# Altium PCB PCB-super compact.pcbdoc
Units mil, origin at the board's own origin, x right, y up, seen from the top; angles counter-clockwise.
Board outline 792.4 x 401.6 mil, 2 copper layers (Top Layer, Bottom Layer), stack 62.2 mil thick; 12 components, 10 nets, 38 pads, 0 vias.
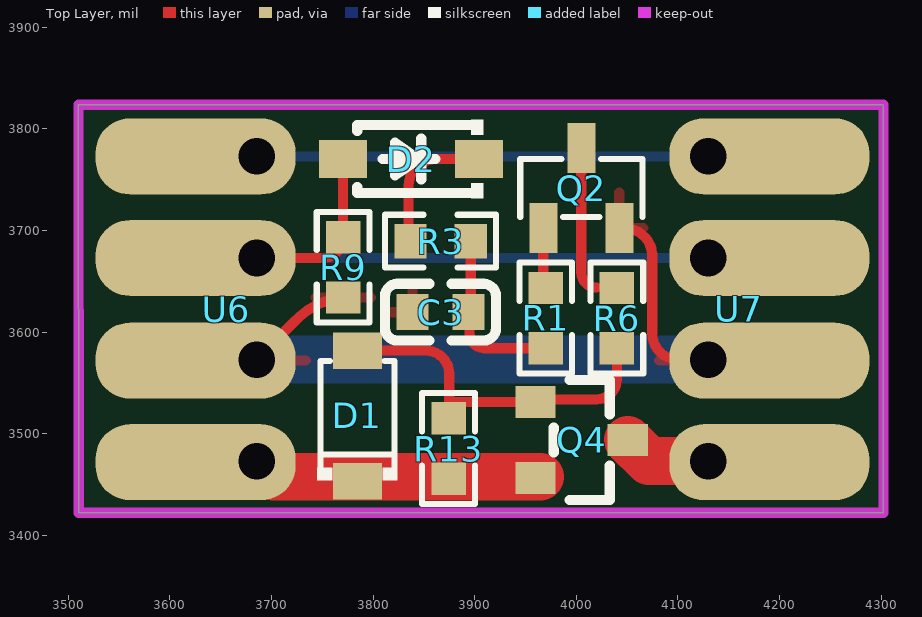
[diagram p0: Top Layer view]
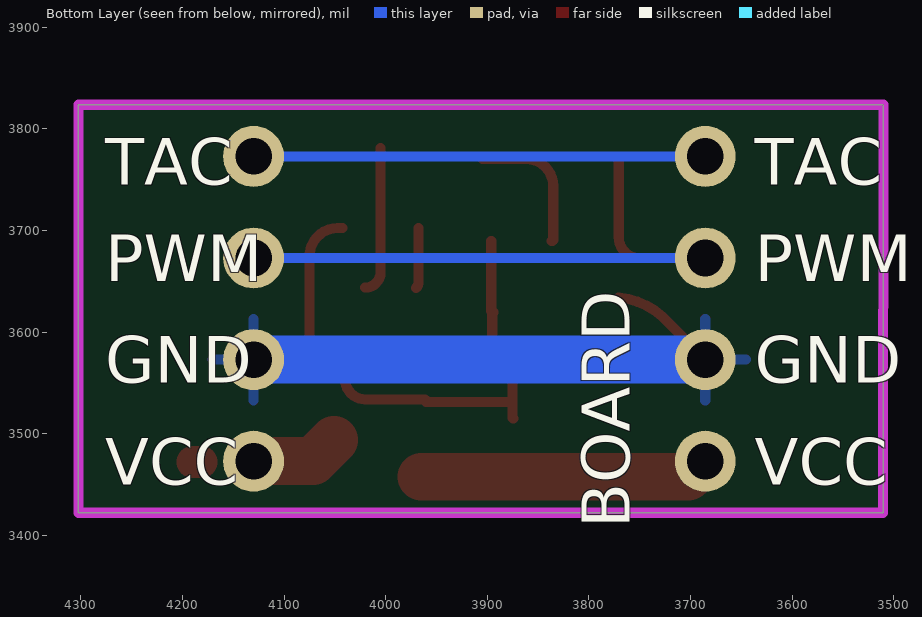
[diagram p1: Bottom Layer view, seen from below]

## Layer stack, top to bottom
Top Solder Mask Layer: solder mask 0.4, Dk 3.3
Top Layer: signal copper 1.4
Dielectric1: surface 59.4, FR4, Dk 4.5
Bottom Layer: signal copper 1.4
Bottom Solder Mask Layer: solder mask 0.4, Dk 3.3

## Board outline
3510,3823.8 4302.4,3823.8 4302.4,3422.2 3510.4,3422.2

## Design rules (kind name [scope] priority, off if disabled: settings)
BoardOutlineClearance copperThickness1oz [All] p0: genericclearance=10 ignorepadtopadclearanceinfootprint=FALSE except(0: Arc-SplitContinuation Track-SplitContinuation SMDPad-SplitContinuation THPad-SplitContinuation Via-SplitContinuation Fill-SplitContinuation Poly-SplitContinuation Region-SplitContinuation Text-SplitContinuation)
BoardOutlineClearance Plane_innerPlane [All] p0: genericclearance=10 ignorepadtopadclearanceinfootprint=FALSE except(0: Arc-SplitContinuation Track-SplitContinuation SMDPad-SplitContinuation THPad-SplitContinuation Via-SplitContinuation Fill-SplitContinuation Poly-SplitContinuation Region-SplitContinuation Text-SplitContinuation)
BoardOutlineClearance Copper_copperRegion [All] p0: genericclearance=10 ignorepadtopadclearanceinfootprint=FALSE except(0: Arc-SplitContinuation Track-SplitContinuation SMDPad-SplitContinuation THPad-SplitContinuation Via-SplitContinuation Fill-SplitContinuation Poly-SplitContinuation Region-SplitContinuation Text-SplitContinuation)
BoardOutlineClearance otherClearance [All] p0: genericclearance=10 ignorepadtopadclearanceinfootprint=FALSE except(0: Arc-SplitContinuation Track-SplitContinuation SMDPad-SplitContinuation THPad-SplitContinuation Via-SplitContinuation Fill-SplitContinuation Poly-SplitContinuation Region-SplitContinuation Text-SplitContinuation)
Clearance copperThickness1oz [All] p1: gap=7 ignorepadtopadclearanceinfootprint=FALSE
Clearance Plane_innerPlane [All] p1: gap=7 ignorepadtopadclearanceinfootprint=FALSE
Clearance Copper_copperRegion [All] p1: gap=7 ignorepadtopadclearanceinfootprint=FALSE
Clearance otherClearance [All] p1: gap=7 ignorepadtopadclearanceinfootprint=FALSE
DiffPairsRouting differentialPair [All] p1: maxuncoupledlength=10 minlimit=5.9843 maxlimit=Infinity mostfreqgap=5.9843 toplayer_minwidth=5 toplayer_prefwidth=10 toplayer_maxwidth=100 bottomlayer_minwidth=5 bottomlayer_prefwidth=10 bottomlayer_maxwidth=100
PasteMaskExpansion pasteMaskExpansion [All] p1: expansion=0
PlaneConnect innerPlane [All] p1: planeconnectstyle=Relief reliefexpansion=20 reliefentries=4 reliefconductorwidth=10 reliefairgap=10
PolygonConnect copperRegion [All] p1: connectstyle=Relief reliefentries=4 reliefconductorwidth=10 polygonreliefangle="90 Angle" airgapwidth=10
RoutingVias viaSize [All] p1: viastyle="Through Hole" holewidth=12.0078 minholewidth=11.811 maxholewidth=248.0314 width=12.0078 minwidth=11.811 maxwidth=248.0314
RoutingVias viaSize2oz [All] p1: viastyle="Through Hole" holewidth=23.622 minholewidth=19.685 maxholewidth=248.0314 width=23.622 minwidth=19.685 maxwidth=248.0314
RoutingVias "no vias" [All] p1: viastyle="Through Hole" holewidth=0.3938 minholewidth=0.3938 maxholewidth=0.3938 width=0.3938 minwidth=0.3938 maxwidth=0.3938
SolderMaskExpansion solderMaskExpansion [IsVia] p1: useseparateexpansions=TRUE expansion=-1000 expansionbottom=-1000
SolderMaskExpansion solderMaskExpansion [All] p2: useseparateexpansions=TRUE expansion=2.0079 expansionbottom=2.0079
Width copperThickness1oz [All] p1: maxlimit=100 minlimit=5 preferedwidth=10
Width thickTrack [All] p1: maxlimit=31 minlimit=31 preferedwidth=31
Width thickerTrack [All] p1: maxlimit=100 minlimit=47 preferedwidth=47

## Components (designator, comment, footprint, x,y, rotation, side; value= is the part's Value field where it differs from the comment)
C3 "47nF" C0603 3866.4,3619.6 r0 top
D1 "MMSZ5240B" SOD-123_L2.7-W1.6-LS3.7-RD 3784.6,3517.4 r90 top
D2 "B5819W SL" SOD-123_L2.7-W1.6-LS3.7-RD-1 3837.5,3770.3 r180 top
Q2 "SS8050(RANGE:200-350)" SOT-23-3_L2.9-W1.3-P1.90-LS2.4-BR 4005,3741.8 r270 top
Q4 "AO3401A" SOT-23_L2.9-W1.3-P1.90-LS2.4-BR 4005.4,3493.8 r180 top
R1 "10kΩ" R0603#1 3970,3613.8 r90 top
R3 "1kΩ" R0603#2 3866.4,3689.5 r0 top
R6 "10kΩ" R0603#2 4040,3613.8 r270 top
R9 "10kΩ" R0603#1 3770.6,3663.8 r90 top
R13 "20kΩ" R0603#3 3874.4,3485.4 r270 top
U6 "" "4P solder pads" 3675.4,3619.9 r0 top
U7 "" "4P solder pads mirrored" 4195,3619.9 r0 top

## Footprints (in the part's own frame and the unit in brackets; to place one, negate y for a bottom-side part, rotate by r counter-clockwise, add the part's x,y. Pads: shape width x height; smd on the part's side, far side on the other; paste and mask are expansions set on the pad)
"4P solder pads" [mil]
  rrect90% 196.9x74.8 smd: 1(-50,153) 2(-50,53) 3(-50,-48) 4(-50,-148)
  round 60 hole 36: 1(10,153) 2(10,53) 3(10,-47) 4(10,-147)
"4P solder pads mirrored" [mil]
  round 60 hole 36: 1(-65,153) 2(-65,53) 3(-65,-47) 4(-65,-147)
  rrect90% 196.9x74.8 smd: 1(-5,153) 2(-5,53) 3(-5,-48) 4(-5,-148)
C0603 [mil]
  rect 31.5x35.4 smd: 1(-27.5,0) 2(27.6,0)
  silkscreen extent -55,-28 55,28
R0603#1 [mil]
  rect 31.8x34 smd paste-3937 mask+2: 1(-29.7,0) 2(29.6,0)
  silkscreen extent -54,-26 54,26
R0603#2 [mil]
  rect 31.8x34 smd paste-3937 mask+2: 1(-29.6,0) 2(29.7,0)
  silkscreen extent -54,-26 54,26
R0603#3 [mil]
  rect 31.8x34 smd paste-3937 mask+2: 1(-29.7,0) 2(29.7,0)
  silkscreen extent -55,-26 55,26
SOD-123_L2.7-W1.6-LS3.7-RD [mil]
  rect 35.8x48 smd: 1(-64.3,0) 2(64.4,0)
  silkscreen extent -63,-39 54,40
SOD-123_L2.7-W1.6-LS3.7-RD-1 [mil]
  rect 47.2x37.4 smd: 1(-66.9,0) 2(66.9,0)
  silkscreen extent -71,-39 53,38
SOT-23-3_L2.9-W1.3-P1.90-LS2.4-BR [mil]
  rect 49.2x27.6 smd: 1(39.4,-37.4) 2(39.4,37.4) 3(-39.4,0)
  silkscreen extent -29,-60 29,60
SOT-23_L2.9-W1.3-P1.90-LS2.4-BR [mil]
  rect 39.4x31.5 smd: 1(45.3,-37.4) 2(45.3,37.4) 3(-45.3,0)
  silkscreen extent -28,-59 28,59

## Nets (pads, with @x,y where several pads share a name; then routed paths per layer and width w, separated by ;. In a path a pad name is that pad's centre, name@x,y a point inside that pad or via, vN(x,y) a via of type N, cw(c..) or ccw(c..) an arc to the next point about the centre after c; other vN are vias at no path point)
$1N3: C3.2 R1.1 R3.2 | length 175.8
  Top Layer w10: C3.2@3894,3619.5 cw(c3894,3618.5) 3895,3618.5 3895,3598.8 ccw(c3909.7,3598.8) 3909.7,3584.1 R1.1 ; C3.2 ccw(c3894,3621.7) 3896.1,3621.7 R3.2
$1N2590: Q2.1 R1.2 | length 59.6
  Top Layer w10: Q2.1 3967.6,3649.2 ccw(c3975.8,3649.2) R1.2
$1N6630: D2.1 R3.1 | length 139.9
  Top Layer w10: R3.1 cw(c3836.8,3691.3) 3835,3691.3 3835,3743.8 cw(c3861.5,3743.8) 3861.5,3770.3 D2.1
$1N7011: D1.2 Q4.1 R6.2 R13.1 | length 357
  Top Layer w10: D1.2 3852,3581.8 cw(c3852,3558.8) 3875,3558.8 3875,3533.4 ; R13.1 ccw(c3874.4,3515.7) 3875,3515.7 3875,3533.4 ; R6.2 4040,3553.8 cw(c4020,3553.8) 4020,3533.8 3962.7,3533.8 ccw(c3962.7,3531.2) Q4.1 3877.2,3531.2 cw(c3877.2,3533.4) 3875,3533.4
$1N7284: Q2.3 R6.1 | length 146
  Top Layer w10: Q2.3 4005,3658.8 ccw(c4020,3658.8) 4020,3643.8
$1N13751: U6.1 U7.1 | length 444.6
  Bottom Layer w10: U6.1@3685.4,3772.9 U7.1@4130,3772.9
GND: C3.1 Q2.2 R9.1 U6.3 U7.3 | length 746.5
  Top Layer w10: U6.3@3685.4,3572.9 3721.1,3608.6 ; 3721.08,3608.67 cw(c3777.9,3559.1) R9.1@3770.54,3634.14 ; Q2.2 4047.4,3702.4 cw(c4047.4,3675) 4074.74,3676.86 ; 4074.8,3676.9 4074.8,3608.7 4074.8,3608.6 4074.8,3598.6 ccw(c4100.6,3598.6) U7.3@4100.6,3572.8 ; U7.3@4100.6,3572.9 U7.3@4130,3572.9
  Bottom Layer w47.2: U6.3@3685.4,3572.9 U7.3@4130,3572.9
PWM: D2.2 R9.2 U6.2 U7.2 | length 618.5
  Top Layer w10: U6.2@3685.4,3672.9 3750,3672.9 ; 3750,3672.8 ccw(c3750,3693.4) R9.2 D2.2
  Bottom Layer w10: U6.2@3685.4,3672.9 U7.2@4130,3672.9
VCC-IN: D1.1 Q4.2 R13.2 U6.4 | length 282
  Top Layer w47.2: U6.4@3688.3,3471.6 3702.2,3457.6 Q4.2@3964.5,3457.6
VCC-OUT: Q4.3 U7.4 | length 96.9
  Top Layer w31.5: U7.4@4181.1,3471.9 U7.4@4190,3471.9
  Top Layer w47.2: Q4.3 4071.6,3472.9 U7.4@4130,3472.9

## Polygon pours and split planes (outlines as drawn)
GND on Top Layer (solid, remove dead copper, pour order 0): 3000,4563.8 3000,3168.8 5585,3168.8 5585,4563.8
GND on Bottom Layer (solid, remove dead copper, pour order 2): 3047.5,4395 3047.5,3000 5632.5,3000 5632.5,4395

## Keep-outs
Board Outline Layer:
  the board outline again, w10

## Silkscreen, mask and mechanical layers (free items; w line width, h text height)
Bottom Silkscreen Layer:
  text "BOARD" at 3759.6,3406.9 h47.2 r270
  text "FAN" at 3984.6,3312.4 h47.2 r90

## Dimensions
3505,3914.3 to 4292.7,3914.3 on Document Layer
4585,3813.8 to 4585,3415.2 on Document Layer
